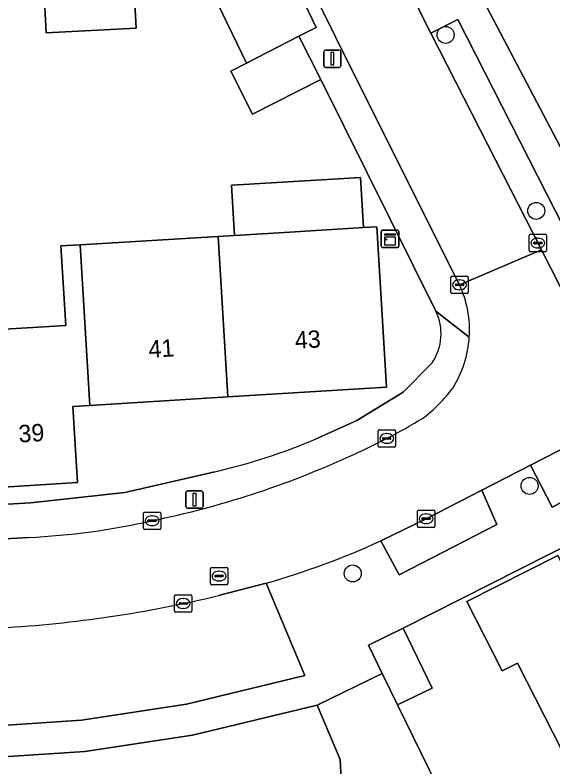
# Model space of a CAD drawing. Extents: x 158455 to 159797, y 387218 to 388672.
# Drawn here: x 159070.47 to 159101.4, y 387805.69 to 387848.94 of the extents above; entities that cross this region are included whole.
import ezdxf

# ---------------------------------------------------------------- set-up
doc = ezdxf.new("R2010")
doc.units = 0
for name, color, linetype in [('IMGEO_Boom', 7, 'Continuous'), ('IMGEO_Erf', 7, 'Continuous'), ('IMGEO_Kast', 7, 'Continuous'), ('IMGEO_Kolk', 7, 'Continuous'), ('IMGEO_Lichtmast', 7, 'Continuous'), ('IMGEO_Pand', 7, 'Continuous'), ('IMGEO_Pand_nummerreeks', 7, 'Continuous'), ('IMGEO_Parkeervlak_open', 7, 'Continuous'), ('IMGEO_Rijbaan_lokaal_open', 7, 'Continuous'), ('IMGEO_Rioolput', 7, 'Continuous'), ('IMGEO_Voetpad_open', 7, 'Continuous')]:
    doc.layers.add(name, color=color, linetype=linetype)

msp = doc.modelspace()

# ---------------------------------------------------------------- linework, layer by layer
at = {"layer": 'IMGEO_Boom'}
for centre in [(159095.232, 387847.802), (159100.442, 387837.68), (159100.061, 387821.859), (159089.887, 387816.824)]:
    msp.add_circle(centre, 0.489, dxfattribs=at)
at = {"layer": 'IMGEO_Erf'}
for points in [[(159092.754, 387855.475), (159095.538, 387850.134), (159096.822, 387850.902), (159111.482, 387823.018), (159136.509, 387836.307), (159127.073, 387854.722), (159124.966, 387853.636), (159123.072, 387857.314), (159125.179, 387858.399), (159112.244, 387883.827)], [(159088.062, 387845.241), (159084.135, 387843.24), (159082.872, 387845.718), (159083.781, 387846.181), (159080.472, 387853.067), (159077.184, 387852.877), (159077.431, 387848.192), (159072.264, 387847.92), (159071.989, 387853.144), (159066.162, 387852.756), (159066.316, 387849.856), (159062.418, 387849.649), (159056.491, 387849.334), (159056.337, 387852.234), (159052.566, 387852.034), (159052.594, 387851.551), (159054.31, 387821.544), (159056.359, 387820.007), (159071.359, 387820.892), (159076.793, 387821.476), (159081.964, 387822.669)], [(159094.669, 387831.91), (159088.062, 387845.241)], [(159068.929, 387830.817), (159073.389, 387831.088), (159073.11, 387835.661), (159074.208, 387835.728), (159082.143, 387836.21), (159083.094, 387836.268), (159082.918, 387839.153), (159083.603, 387839.195), (159090.335, 387839.604), (159090.511, 387836.72), (159091.272, 387836.766), (159091.834, 387827.529), (159082.707, 387826.974), (159074.771, 387826.491), (159073.802, 387826.432), (159074.069, 387822.046), (159069.481, 387821.767)], [(159087.78, 387824.563), (159090.126, 387825.617), (159092.787, 387827.25), (159094.448, 387828.929)], [(159089.4, 387801.648), (159089.16, 387806.127), (159087.85, 387809.249), (159080.674, 387807.513), (159074.492, 387806.573), (159067.137, 387806.107), (159067.081, 387807.066), (159065.938, 387809.009), (159065.131, 387808.962), (159059.213, 387808.616), (159057.349, 387806.284), (159057.868, 387797.348)]]:
    msp.add_lwpolyline(points, dxfattribs=at)
for points in [[(159113.282, 387814.48), (159106.206, 387820.459), (159092.791, 387813.673), (159094.46, 387810.225), (159092.457, 387809.255), (159095.646, 387802.766), (159096.135, 387800.968), (159098.415, 387801.099), (159098.562, 387798.543), (159098.849, 387793.531), (159096.569, 387793.4), (159096.854, 387788.441), (159100.741, 387788.649), (159100.859, 387786.445), (159103.731, 387786.611), (159109.748, 387786.958), (159109.459, 387790.338), (159122.076, 387796.798), (159122.24, 387796.882)], [(159099.358, 387811.655), (159098.477, 387811.21), (159096.457, 387815.209), (159101.688, 387817.851), (159103.708, 387813.852), (159109.259, 387816.656), (159111.784, 387811.658), (159114.224, 387806.828), (159116.674, 387801.979), (159119.248, 387796.884), (159111.233, 387792.835), (159109.221, 387791.818), (159109.208, 387790.967), (159105.295, 387790.761), (159103.165, 387794.978), (159106.053, 387796.436), (159108.73, 387797.788), (159108.673, 387797.901), (159106.231, 387802.735), (159103.787, 387807.574), (159101.927, 387806.624)]]:
    msp.add_lwpolyline(points, close=True, dxfattribs=at)
for centre, radius, start, end in [((159092.007, 387830.609), 2.963, 325.4668, 26.0533), ((159074.143, 387856.561), 34.783, 282.9937, 293.0823)]:
    msp.add_arc(centre, radius, start, end, dxfattribs=at)
at = {"layer": 'IMGEO_Kast'}
for p, q in [((159091.532, 387835.646), (159091.532, 387836.487)), ((159091.532, 387836.487), (159091.532, 387835.646)), ((159091.607, 387836.571), (159092.448, 387836.571)), ((159092.448, 387836.571), (159091.607, 387836.571)), ((159092.532, 387836.496), (159092.532, 387835.655)), ((159092.532, 387835.655), (159092.532, 387836.496)), ((159092.457, 387835.571), (159091.616, 387835.571)), ((159091.616, 387835.571), (159092.457, 387835.571))]:
    msp.add_line(p, q, dxfattribs=at)
for points in [[(159091.727, 387836.361), (159092.327, 387836.361), (159092.327, 387836.276), (159091.727, 387836.276), (159091.727, 387836.361)], [(159091.727, 387836.186), (159092.327, 387836.186), (159092.327, 387835.697), (159091.727, 387835.697), (159091.727, 387836.186)]]:
    msp.add_lwpolyline(points, dxfattribs=at)
msp.add_circle((159091.811, 387836.035), 0.0377, dxfattribs=at)
for centre, start, end in [((159091.61, 387836.493), 92.4484, 184.2845), ((159091.61, 387836.493), 92.4484, 184.2845), ((159092.454, 387836.493), 2.4484, 94.2845), ((159092.454, 387836.493), 2.4484, 94.2845), ((159091.61, 387835.649), 182.4484, 274.2845), ((159091.61, 387835.649), 182.4484, 274.2845), ((159092.454, 387835.649), 272.4484, 4.2845), ((159092.454, 387835.649), 272.4484, 4.2845)]:
    msp.add_arc(centre, 0.0779, start, end, dxfattribs=at)
at = {"layer": 'IMGEO_Kolk'}
for p, q in [((159100.035, 387835.403), (159100.035, 387836.255)), ((159100.11, 387836.329), (159100.962, 387836.329)), ((159100.523, 387836.109), (159100.548, 387836.109)), ((159101.036, 387836.255), (159101.036, 387835.403)), ((159100.294, 387835.823), (159100.294, 387835.835)), ((159100.732, 387835.786), (159100.334, 387835.786)), ((159100.337, 387835.872), (159100.735, 387835.872)), ((159100.546, 387835.549), (159100.521, 387835.549)), ((159100.778, 387835.835), (159100.778, 387835.823)), ((159100.962, 387835.329), (159100.11, 387835.329)), ((159095.53, 387832.999), (159095.53, 387833.851)), ((159095.605, 387833.925), (159096.457, 387833.925)), ((159096.531, 387833.851), (159096.531, 387832.999)), ((159095.789, 387833.419), (159095.789, 387833.431)), ((159096.227, 387833.382), (159095.829, 387833.382)), ((159095.832, 387833.468), (159096.23, 387833.468)), ((159096.018, 387833.705), (159096.043, 387833.705)), ((159096.273, 387833.431), (159096.273, 387833.419)), ((159096.041, 387833.145), (159096.016, 387833.145)), ((159096.457, 387832.925), (159095.605, 387832.925)), ((159091.346, 387824.16), (159091.346, 387825.012)), ((159091.421, 387825.086), (159092.273, 387825.086)), ((159091.834, 387824.866), (159091.859, 387824.866)), ((159092.347, 387825.012), (159092.347, 387824.16)), ((159091.605, 387824.58), (159091.605, 387824.592)), ((159092.043, 387824.543), (159091.645, 387824.543)), ((159091.648, 387824.629), (159092.046, 387824.629)), ((159091.857, 387824.306), (159091.832, 387824.306)), ((159092.089, 387824.592), (159092.089, 387824.58)), ((159092.273, 387824.086), (159091.421, 387824.086)), ((159093.685, 387820.469), (159094.537, 387820.469)), ((159077.855, 387819.429), (159077.855, 387820.281)), ((159077.93, 387820.355), (159078.782, 387820.355)), ((159078.343, 387820.135), (159078.368, 387820.135)), ((159078.856, 387820.281), (159078.856, 387819.429)), ((159093.61, 387819.543), (159093.61, 387820.395)), ((159093.869, 387819.963), (159093.869, 387819.975)), ((159093.912, 387820.012), (159094.31, 387820.012)), ((159094.098, 387820.249), (159094.123, 387820.249)), ((159094.353, 387819.975), (159094.353, 387819.963)), ((159094.611, 387820.395), (159094.611, 387819.543)), ((159078.114, 387819.849), (159078.114, 387819.861)), ((159078.552, 387819.812), (159078.154, 387819.812)), ((159078.157, 387819.898), (159078.555, 387819.898)), ((159078.366, 387819.575), (159078.341, 387819.575)), ((159078.598, 387819.861), (159078.598, 387819.849)), ((159094.307, 387819.926), (159093.909, 387819.926)), ((159094.121, 387819.689), (159094.096, 387819.689)), ((159078.782, 387819.355), (159077.93, 387819.355)), ((159094.537, 387819.469), (159093.685, 387819.469)), ((159079.642, 387814.667), (159079.642, 387815.519)), ((159079.717, 387815.593), (159080.569, 387815.593)), ((159080.13, 387815.373), (159080.155, 387815.373)), ((159080.643, 387815.519), (159080.643, 387814.667)), ((159079.901, 387815.087), (159079.901, 387815.099)), ((159080.339, 387815.05), (159079.941, 387815.05)), ((159079.944, 387815.136), (159080.342, 387815.136)), ((159080.153, 387814.813), (159080.128, 387814.813)), ((159080.385, 387815.099), (159080.385, 387815.087)), ((159080.569, 387814.593), (159079.717, 387814.593))]:
    msp.add_line(p, q, dxfattribs=at)
for points in [[(159100.035, 387835.403), (159100.035, 387836.255)], [(159100.11, 387836.329), (159100.962, 387836.329)], [(159101.036, 387836.255), (159101.036, 387835.403)], [(159100.962, 387835.329), (159100.11, 387835.329)], [(159095.53, 387832.999), (159095.53, 387833.851)], [(159095.605, 387833.925), (159096.457, 387833.925)], [(159096.531, 387833.851), (159096.531, 387832.999)], [(159096.457, 387832.925), (159095.605, 387832.925)], [(159091.346, 387824.16), (159091.346, 387825.012)], [(159091.421, 387825.086), (159092.273, 387825.086)], [(159092.347, 387825.012), (159092.347, 387824.16)], [(159092.273, 387824.086), (159091.421, 387824.086)], [(159093.685, 387820.469), (159094.537, 387820.469)], [(159077.855, 387819.429), (159077.855, 387820.281)], [(159077.93, 387820.355), (159078.782, 387820.355)], [(159078.856, 387820.281), (159078.856, 387819.429)], [(159093.61, 387819.543), (159093.61, 387820.395)], [(159094.611, 387820.395), (159094.611, 387819.543)], [(159078.782, 387819.355), (159077.93, 387819.355)], [(159094.537, 387819.469), (159093.685, 387819.469)], [(159079.642, 387814.667), (159079.642, 387815.519)], [(159079.717, 387815.593), (159080.569, 387815.593)], [(159080.643, 387815.519), (159080.643, 387814.667)], [(159080.569, 387814.593), (159079.717, 387814.593)]]:
    msp.add_lwpolyline(points, dxfattribs=at)
for centre, radius, start, end in [((159100.112, 387836.253), 0.0765, 91.552, 178.448), ((159100.112, 387836.253), 0.0765, 91.552, 178.448), ((159100.96, 387836.253), 0.0765, 1.552, 88.448), ((159100.96, 387836.253), 0.0765, 1.552, 88.448), ((159100.334, 387835.832), 0.0403, 85.8775, 175.7526), ((159100.331, 387835.822), 0.0366, 178.938, 274.7102), ((159100.735, 387835.829), 0.043, 264.8664, 352.4533), ((159100.739, 387835.834), 0.0386, 1.7309, 96.639), ((159100.112, 387835.405), 0.0765, 181.552, 268.448), ((159100.112, 387835.405), 0.0765, 181.552, 268.448), ((159100.96, 387835.405), 0.0765, 271.552, 358.448), ((159100.96, 387835.405), 0.0765, 271.552, 358.448), ((159095.607, 387833.849), 0.0765, 91.552, 178.448), ((159095.607, 387833.849), 0.0765, 91.552, 178.448), ((159096.455, 387833.849), 0.0765, 1.552, 88.448), ((159096.455, 387833.849), 0.0765, 1.552, 88.448), ((159095.829, 387833.428), 0.0403, 85.8775, 175.7526), ((159095.826, 387833.418), 0.0366, 178.938, 274.7102), ((159096.23, 387833.425), 0.043, 264.8664, 352.4533), ((159096.234, 387833.43), 0.0386, 1.7309, 96.639), ((159095.607, 387833.001), 0.0765, 181.552, 268.448), ((159095.607, 387833.001), 0.0765, 181.552, 268.448), ((159096.455, 387833.001), 0.0765, 271.552, 358.448), ((159096.455, 387833.001), 0.0765, 271.552, 358.448), ((159091.423, 387825.01), 0.0765, 91.552, 178.448), ((159091.423, 387825.01), 0.0765, 91.552, 178.448), ((159092.271, 387825.01), 0.0765, 1.552, 88.448), ((159092.271, 387825.01), 0.0765, 1.552, 88.448), ((159091.645, 387824.589), 0.0403, 85.8775, 175.7526), ((159091.642, 387824.579), 0.0366, 178.938, 274.7102), ((159092.046, 387824.586), 0.043, 264.8664, 352.4533), ((159092.05, 387824.591), 0.0386, 1.7309, 96.639), ((159091.423, 387824.162), 0.0765, 181.552, 268.448), ((159091.423, 387824.162), 0.0765, 181.552, 268.448), ((159092.271, 387824.162), 0.0765, 271.552, 358.448), ((159092.271, 387824.162), 0.0765, 271.552, 358.448), ((159093.687, 387820.393), 0.0765, 91.552, 178.448), ((159093.687, 387820.393), 0.0765, 91.552, 178.448), ((159094.535, 387820.393), 0.0765, 1.552, 88.448), ((159094.535, 387820.393), 0.0765, 1.552, 88.448), ((159077.932, 387820.279), 0.0765, 91.552, 178.448), ((159077.932, 387820.279), 0.0765, 91.552, 178.448), ((159078.78, 387820.279), 0.0765, 1.552, 88.448), ((159078.78, 387820.279), 0.0765, 1.552, 88.448), ((159093.909, 387819.972), 0.0403, 85.8775, 175.7526), ((159094.314, 387819.974), 0.0386, 1.7309, 96.639), ((159078.154, 387819.858), 0.0403, 85.8775, 175.7526), ((159078.151, 387819.848), 0.0366, 178.938, 274.7102), ((159078.555, 387819.855), 0.043, 264.8664, 352.4533), ((159078.559, 387819.86), 0.0386, 1.7309, 96.639), ((159093.687, 387819.545), 0.0765, 181.552, 268.448), ((159093.687, 387819.545), 0.0765, 181.552, 268.448), ((159093.906, 387819.962), 0.0366, 178.938, 274.7102), ((159094.31, 387819.969), 0.043, 264.8664, 352.4533), ((159094.535, 387819.545), 0.0765, 271.552, 358.448), ((159094.535, 387819.545), 0.0765, 271.552, 358.448), ((159077.932, 387819.431), 0.0765, 181.552, 268.448), ((159077.932, 387819.431), 0.0765, 181.552, 268.448), ((159078.78, 387819.431), 0.0765, 271.552, 358.448), ((159078.78, 387819.431), 0.0765, 271.552, 358.448), ((159079.719, 387815.517), 0.0765, 91.552, 178.448), ((159079.719, 387815.517), 0.0765, 91.552, 178.448), ((159080.567, 387815.517), 0.0765, 1.552, 88.448), ((159080.567, 387815.517), 0.0765, 1.552, 88.448), ((159079.941, 387815.096), 0.0403, 85.8775, 175.7526), ((159079.938, 387815.086), 0.0366, 178.938, 274.7102), ((159080.342, 387815.093), 0.043, 264.8664, 352.4533), ((159080.346, 387815.098), 0.0386, 1.7309, 96.639), ((159079.719, 387814.669), 0.0765, 181.552, 268.448), ((159079.719, 387814.669), 0.0765, 181.552, 268.448), ((159080.567, 387814.669), 0.0765, 271.552, 358.448), ((159080.567, 387814.669), 0.0765, 271.552, 358.448)]:
    msp.add_arc(centre, radius, start, end, dxfattribs=at)
for centre, major_axis, ratio, start_param, end_param in [((159100.522, 387835.829), (-0.387, 0.002), 0.722429, 4.712389, 7.853982), ((159100.547, 387835.829), (-0.39, 0.002), 0.717154, 1.570796, 4.712389), ((159096.017, 387833.425), (-0.387, 0.002), 0.722429, 4.712389, 7.853982), ((159096.042, 387833.425), (-0.39, 0.002), 0.717154, 1.570796, 4.712389), ((159091.833, 387824.586), (-0.387, 0.002), 0.722429, 4.712389, 7.853982), ((159091.858, 387824.586), (-0.39, 0.002), 0.717154, 1.570796, 4.712389), ((159078.342, 387819.855), (-0.387, 0.002), 0.722429, 4.712389, 7.853982), ((159078.367, 387819.855), (-0.39, 0.002), 0.717154, 1.570796, 4.712389), ((159094.097, 387819.969), (-0.387, 0.002), 0.722429, 4.712389, 7.853982), ((159094.122, 387819.969), (-0.39, 0.002), 0.717154, 1.570796, 4.712389), ((159080.129, 387815.093), (-0.387, 0.002), 0.722429, 4.712389, 7.853982), ((159080.154, 387815.093), (-0.39, 0.002), 0.717154, 1.570796, 4.712389)]:
    msp.add_ellipse(centre, major_axis=major_axis, ratio=ratio, start_param=start_param, end_param=end_param, dxfattribs=at)
at = {"layer": 'IMGEO_Lichtmast'}
for p, q in [((159088.223, 387846.031), (159088.223, 387846.831)), ((159088.223, 387846.831), (159088.223, 387846.031)), ((159088.323, 387846.931), (159089.113, 387846.931)), ((159089.113, 387846.931), (159088.323, 387846.931)), ((159089.213, 387846.831), (159089.213, 387846.031)), ((159089.213, 387846.031), (159089.213, 387846.831)), ((159089.113, 387845.931), (159088.323, 387845.931)), ((159088.323, 387845.931), (159089.113, 387845.931)), ((159080.291, 387820.673), (159080.291, 387821.473)), ((159080.291, 387821.473), (159080.291, 387820.673)), ((159080.391, 387821.573), (159081.181, 387821.573)), ((159081.181, 387821.573), (159080.391, 387821.573)), ((159081.281, 387821.473), (159081.281, 387820.673)), ((159081.281, 387820.673), (159081.281, 387821.473)), ((159081.181, 387820.573), (159080.391, 387820.573)), ((159080.391, 387820.573), (159081.181, 387820.573))]:
    msp.add_line(p, q, dxfattribs=at)
for points in [[(159088.643, 387846.806), (159088.793, 387846.806), (159088.793, 387846.056), (159088.643, 387846.056), (159088.643, 387846.806)], [(159080.711, 387821.448), (159080.861, 387821.448), (159080.861, 387820.698), (159080.711, 387820.698), (159080.711, 387821.448)]]:
    msp.add_lwpolyline(points, dxfattribs=at)
for centre, start, end in [((159088.323, 387846.831), 90, 180), ((159088.323, 387846.831), 90, 180), ((159089.113, 387846.831), 0, 90), ((159089.113, 387846.831), 360, 90), ((159088.323, 387846.031), 180, 270), ((159088.323, 387846.031), 180, 270), ((159089.113, 387846.031), 270, 0), ((159089.113, 387846.031), 270, 0), ((159080.391, 387821.473), 90, 180), ((159080.391, 387821.473), 90, 180), ((159081.181, 387821.473), 0, 90), ((159081.181, 387821.473), 360, 90), ((159080.391, 387820.673), 180, 270), ((159080.391, 387820.673), 180, 270), ((159081.181, 387820.673), 270, 0), ((159081.181, 387820.673), 270, 0)]:
    msp.add_arc(centre, 0.1, start, end, dxfattribs=at)
at = {"layer": 'IMGEO_Pand'}
for points in [[(159077.184, 387852.877), (159077.156, 387853.416), (159071.989, 387853.144), (159072.264, 387847.92), (159077.431, 387848.192)], [(159088.062, 387845.241), (159086.799, 387847.719), (159083.781, 387846.181), (159082.872, 387845.718), (159084.135, 387843.24)], [(159083.603, 387839.195), (159082.918, 387839.153), (159083.094, 387836.268), (159086.282, 387836.462), (159090.511, 387836.72), (159090.335, 387839.604)], [(159091.272, 387836.766), (159090.511, 387836.72), (159086.282, 387836.462), (159083.094, 387836.268), (159082.143, 387836.21), (159082.707, 387826.974), (159091.834, 387827.529)], [(159082.707, 387826.974), (159082.143, 387836.21), (159074.208, 387835.728), (159074.771, 387826.491)], [(159074.208, 387835.728), (159073.11, 387835.661), (159073.389, 387831.088), (159068.929, 387830.817), (159069.481, 387821.767), (159074.069, 387822.046), (159073.802, 387826.432), (159074.771, 387826.491)], [(159111.784, 387811.658), (159109.259, 387816.656), (159103.708, 387813.852), (159101.688, 387817.851), (159096.457, 387815.209), (159098.477, 387811.21), (159099.358, 387811.655), (159101.927, 387806.624), (159103.787, 387807.574)], [(159092.791, 387813.673), (159090.788, 387812.703), (159091.585, 387811.056), (159092.457, 387809.255), (159094.46, 387810.225)]]:
    msp.add_lwpolyline(points, close=True, dxfattribs=at)
at = {"layer": 'IMGEO_Parkeervlak_open'}
for points in [[(159083.781, 387846.181), (159086.799, 387847.719), (159087.788, 387848.223), (159084.115, 387855.932), (159080.05, 387853.946), (159080.472, 387853.067)], [(159095.941, 387848.682), (159094.386, 387847.902), (159097.219, 387842.345), (159100.739, 387835.43), (159105.605, 387825.871), (159106.674, 387826.42), (159107.152, 387826.665)], [(159105.605, 387825.871), (159100.118, 387823.053), (159101.361, 387820.634), (159107.917, 387824.001), (159106.674, 387826.42)], [(159097.315, 387821.614), (159094.108, 387819.967), (159091.512, 387818.695), (159092.565, 387816.747), (159098.179, 387819.643)]]:
    msp.add_lwpolyline(points, close=True, dxfattribs=at)
msp.add_lwpolyline([(159069.667, 387813.692), (159062.99, 387813.329), (159063.076, 387811.726), (159064.976, 387811.829), (159069.778, 387812.091), (159069.994, 387808.102), (159074.298, 387808.375), (159080.324, 387809.292), (159087.141, 387810.941), (159084.91, 387816.257), (159082.18, 387815.552)], dxfattribs=at)
msp.add_arc((159065.553, 387884.386), 70.814, 273.33022, 283.57947, dxfattribs=at)
at = {"layer": 'IMGEO_Rijbaan_lokaal_open'}
for points in [[(159097.219, 387842.345), (159094.386, 387847.902), (159093.927, 387848.803), (159089.38, 387858.305), (159084.697, 387856.519), (159084.86, 387856.152), (159085.025, 387855.786)], [(159087.872, 387849.785), (159089.879, 387845.718), (159096.028, 387833.429), (159100.739, 387835.43), (159097.219, 387842.345)], [(159091.512, 387818.695), (159094.108, 387819.967), (159097.315, 387821.614), (159100.118, 387823.053), (159105.605, 387825.871), (159100.739, 387835.43), (159096.028, 387833.429)], [(159071.242, 387818.891), (159056.47, 387818.052), (159048.458, 387817.597), (159048.177, 387817.579), (159048.473, 387812.539), (159048.611, 387812.548), (159062.99, 387813.329), (159069.667, 387813.692)], [(159082.18, 387815.552), (159084.91, 387816.257)], [(159095.646, 387802.766), (159092.457, 387809.255), (159091.585, 387811.056), (159087.85, 387809.249), (159089.16, 387806.127), (159089.4, 387801.648)]]:
    msp.add_lwpolyline(points, dxfattribs=at)
for centre, radius, start, end in [((159090.401, 387830.811), 6.206, 356.2742, 24.949), ((159090.414, 387830.814), 6.193, 327.51, 356.2449), ((159088.752, 387832.569), 8.558, 307.1222, 323.5727), ((159073.706, 387859.469), 39.316, 293.9654, 300.9341), ((159067.706, 387871.781), 53.006, 281.598, 294.4861), ((159069.268, 387860.174), 41.33, 272.7379, 282.7127), ((159071.328, 387863.194), 48.862, 286.1385, 294.3981), ((159065.553, 387884.386), 70.814, 273.33022, 283.57947)]:
    msp.add_arc(centre, radius, start, end, dxfattribs=at)
at = {"layer": 'IMGEO_Rioolput'}
for p, q in [((159081.703, 387816.246), (159081.703, 387817.098)), ((159081.778, 387817.172), (159082.63, 387817.172)), ((159082.191, 387816.952), (159082.216, 387816.952)), ((159082.704, 387817.098), (159082.704, 387816.246)), ((159081.962, 387816.666), (159081.962, 387816.678)), ((159082.4, 387816.629), (159082.002, 387816.629)), ((159082.005, 387816.715), (159082.403, 387816.715)), ((159082.446, 387816.678), (159082.446, 387816.666)), ((159082.63, 387816.172), (159081.778, 387816.172)), ((159082.214, 387816.392), (159082.189, 387816.392))]:
    msp.add_line(p, q, dxfattribs=at)
for points in [[(159081.703, 387816.246), (159081.703, 387817.098)], [(159081.778, 387817.172), (159082.63, 387817.172)], [(159082.704, 387817.098), (159082.704, 387816.246)], [(159082.63, 387816.172), (159081.778, 387816.172)]]:
    msp.add_lwpolyline(points, dxfattribs=at)
for centre, radius, start, end in [((159081.78, 387817.096), 0.0765, 91.552, 178.448), ((159081.78, 387817.096), 0.0765, 91.552, 178.448), ((159082.628, 387817.096), 0.0765, 1.552, 88.448), ((159082.628, 387817.096), 0.0765, 1.552, 88.448), ((159082.002, 387816.675), 0.0403, 85.8775, 175.7526), ((159081.999, 387816.665), 0.0366, 178.938, 274.7102), ((159082.403, 387816.672), 0.043, 264.8664, 352.4533), ((159082.407, 387816.677), 0.0386, 1.7309, 96.639), ((159081.78, 387816.248), 0.0765, 181.552, 268.448), ((159081.78, 387816.248), 0.0765, 181.552, 268.448), ((159082.628, 387816.248), 0.0765, 271.552, 358.448), ((159082.628, 387816.248), 0.0765, 271.552, 358.448)]:
    msp.add_arc(centre, radius, start, end, dxfattribs=at)
for centre, major_axis, ratio, start_param, end_param in [((159082.19, 387816.672), (-0.387, 0.002), 0.722429, 4.712389, 7.853982), ((159082.215, 387816.672), (-0.39, 0.002), 0.717154, 1.570796, 4.712389)]:
    msp.add_ellipse(centre, major_axis=major_axis, ratio=ratio, start_param=start_param, end_param=end_param, dxfattribs=at)
at = {"layer": 'IMGEO_Voetpad_open'}
for points in [[(159086.587, 387865.695), (159088.077, 387861.489), (159089.204, 387858.672), (159089.38, 387858.305), (159093.927, 387848.803), (159094.386, 387847.902), (159095.941, 387848.682), (159107.152, 387826.665), (159106.674, 387826.42), (159107.917, 387824.001), (159101.361, 387820.634), (159100.118, 387823.053), (159097.315, 387821.614), (159098.179, 387819.643), (159092.565, 387816.747), (159091.512, 387818.695)], [(159082.373, 387860.458), (159083.452, 387857.505), (159077.02, 387855.085), (159077.156, 387853.416), (159077.184, 387852.877), (159080.472, 387853.067), (159080.05, 387853.946), (159084.115, 387855.932), (159087.788, 387848.223), (159086.799, 387847.719), (159088.062, 387845.241), (159094.669, 387831.91), (159096.594, 387830.408)], [(159084.91, 387816.257), (159087.141, 387810.941), (159080.324, 387809.292), (159074.298, 387808.375), (159069.994, 387808.102), (159069.778, 387812.091), (159064.976, 387811.829), (159065.131, 387808.962), (159065.938, 387809.009), (159067.081, 387807.066), (159067.137, 387806.107), (159074.492, 387806.573), (159080.674, 387807.513), (159087.85, 387809.249), (159091.585, 387811.056), (159090.788, 387812.703), (159092.791, 387813.673), (159106.206, 387820.459), (159109.81, 387822.282), (159111.482, 387823.018), (159096.822, 387850.902)], [(159089.879, 387845.718), (159087.872, 387849.785)], [(159096.028, 387833.429), (159089.879, 387845.718)], [(159096.594, 387830.408), (159094.669, 387831.91)], [(159094.448, 387828.929), (159092.787, 387827.25), (159090.126, 387825.617), (159087.78, 387824.563)], [(159081.964, 387822.669), (159076.793, 387821.476), (159071.359, 387820.892), (159056.359, 387820.007), (159056.47, 387818.052), (159071.242, 387818.891)]]:
    msp.add_lwpolyline(points, dxfattribs=at)
for centre, radius, start, end in [((159090.401, 387830.811), 6.206, 356.2742, 24.949), ((159092.007, 387830.609), 2.963, 325.4668, 26.0533), ((159090.414, 387830.814), 6.193, 327.51, 356.2449), ((159088.752, 387832.569), 8.558, 307.1222, 323.5727), ((159073.706, 387859.469), 39.316, 293.9654, 300.9341), ((159074.143, 387856.561), 34.783, 282.9937, 293.0823), ((159067.706, 387871.781), 53.006, 281.598, 294.4861), ((159069.268, 387860.174), 41.33, 272.7379, 282.7127), ((159071.328, 387863.194), 48.862, 286.1385, 294.3981)]:
    msp.add_arc(centre, radius, start, end, dxfattribs=at)

# ---------------------------------------------------------------- texts
at = {"layer": 'IMGEO_Pand_nummerreeks'}
for s, rotation, p in [('43', 3.4836, (159086.59, 387829.735)), ('41', 3.4812, (159078.172, 387829.222)), ('39', 3.4799, (159070.698, 387824.351))]:
    msp.add_text(s, height=1, rotation=rotation, dxfattribs=at).set_placement(p)

doc.saveas('drawing.dxf')
